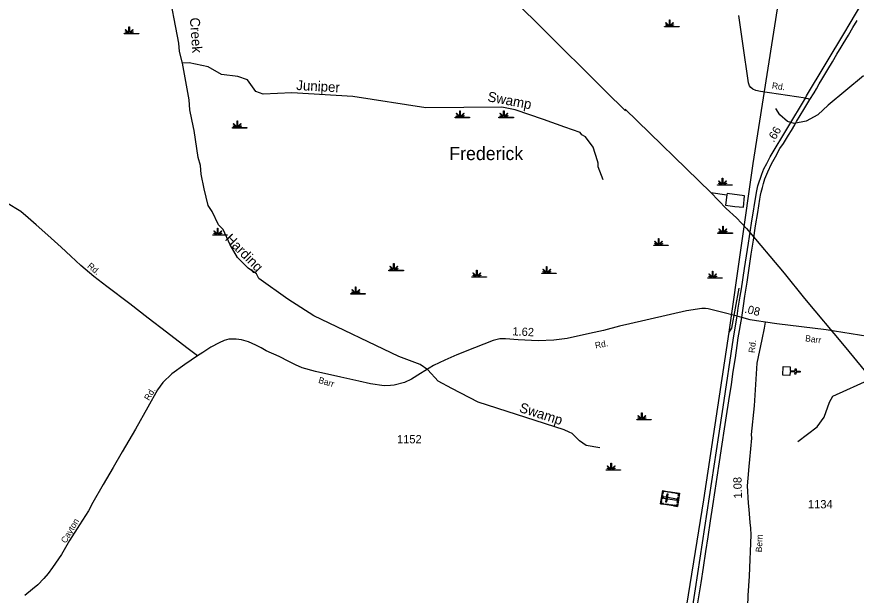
# Model space of a CAD drawing. Extents: x 2532689 to 2764727, y 536648 to 732970.
# Drawn here: x 2549089 to 2561755, y 627049 to 635778 of the extents above; entities that cross this region are included whole.
import ezdxf

# ---------------------------------------------------------------- set-up
doc = ezdxf.new("R2010")
doc.units = 0
for name, color, linetype in [('Exist Civil Demographics Community Label', 7, 'Continuous'), ('Exist Cultural Cemetery CELL', 7, 'Continuous'), ('Exist Cultural Church CELL', 7, 'Continuous'), ('Exist Hydrographic Creek Single Shore', 7, 'Continuous'), ('Exist Hydrographic Creek Single Shore Label', 7, 'Continuous'), ('Exist Hydrographic Swamp CELL', 7, 'Continuous'), ('Exist Hydrographic Swamp Label', 7, 'Continuous'), ('Exist Railroad Mainline', 7, 'Continuous'), ('Exist Railroad Siding', 7, 'Continuous'), ('Exist Road Primary US Divided Attributed', 7, 'Continuous'), ('Exist Road Primary US Mileage Hundredths English Label', 7, 'Continuous'), ('Exist Road Secondary Mileage Hundredths English Label', 7, 'Continuous'), ('Exist Road Secondary Type 51 Attributed', 7, 'Continuous'), ('Exist Road Secondary Type 51 Label', 7, 'Continuous'), ('Exist Road Secondary Type 51 Number Label', 7, 'Continuous'), ('Exist Utilities Electrical Transmission Line', 7, 'Continuous')]:
    doc.layers.add(name, color=color, linetype=linetype)

msp = doc.modelspace()

# ---------------------------------------------------------------- linework, layer by layer
at = {"layer": 'Exist Cultural Cemetery CELL'}
for points in [[(2558804, 628430), (2558835, 628626), (2559087, 628587), (2559056, 628390)], [(2558878, 628620), (2558876, 628609), (2558844, 628614), (2558838, 628574), (2558827, 628575), (2558835, 628627)], [(2558948, 628597), (2558906, 628604), (2558907, 628615), (2558950, 628608)], [(2559014, 628587), (2558971, 628594), (2558973, 628605), (2559015, 628598)], [(2558847, 628423), (2558849, 628434), (2558817, 628439), (2558823, 628479), (2558812, 628481), (2558804, 628430)], [(2558816, 628503), (2558824, 628554), (2558835, 628552), (2558827, 628501)], [(2558850, 628533), (2558847, 628514), (2559047, 628483), (2559050, 628501)], [(2558878, 628460), (2558896, 628457), (2558915, 628573), (2558896, 628576)], [(2559082, 628554), (2559070, 628556), (2559074, 628578), (2559034, 628584), (2559035, 628595), (2559087, 628587)], [(2559053, 628449), (2559067, 628532), (2559078, 628531), (2559065, 628447)], [(2558920, 628411), (2558877, 628418), (2558879, 628429), (2558922, 628423)], [(2558987, 628401), (2558944, 628408), (2558946, 628419), (2558988, 628412)], [(2559061, 628423), (2559049, 628425), (2559046, 628403), (2559006, 628409), (2559004, 628398), (2559056, 628390)]]:
    msp.add_lwpolyline(points, close=True, dxfattribs=at)
at = {"layer": 'Exist Cultural Church CELL'}
msp.add_lwpolyline([(2560760, 630495), (2560757, 630438), (2560833, 630433), (2560835, 630465), (2560851, 630464), (2560849, 630432), (2560909, 630429), (2560908, 630413), (2560848, 630416), (2560846, 630384), (2560830, 630385), (2560832, 630417), (2560756, 630422), (2560752, 630365), (2560646, 630371), (2560654, 630501)], close=True, dxfattribs=at)
at = {"layer": 'Exist Hydrographic Creek Single Shore'}
for points in [[(2551589, 635080), (2551544, 635256), (2551534, 635380), (2551368, 636250), (2551357, 636400), (2551313, 636510), (2551284, 636726), (2551247, 636931), (2551228, 637065), (2551173, 637306), (2551118, 637632), (2551108, 637713), (2550964, 637845), (2550619, 638005), (2550401, 638075), (2548712, 638838)], [(2557357, 634112), (2557038, 634230), (2556610, 634374), (2556410, 634412), (2555260, 634405), (2554157, 634577), (2553239, 634628), (2552806, 634611), (2552697, 634652), (2552569, 634824), (2552426, 634878), (2552176, 634907), (2551974, 635020), (2551689, 635081), (2551589, 635080)], [(2551757, 634109), (2551702, 634376), (2551691, 634523), (2551589, 635080)], [(2561864, 634888), (2561331, 634443), (2561175, 634299), (2561002, 634204), (2560819, 634167), (2560719, 634199), (2560600, 634299), (2560540, 634395)], [(2557425, 629512), (2557349, 629545), (2556050, 629962), (2555655, 630171), (2555448, 630278), (2555292, 630451), (2555173, 630530), (2554854, 630649), (2553573, 631266), (2553180, 631517), (2552740, 631827), (2552706, 631901), (2552579, 631982), (2552418, 632146), (2552306, 632335), (2552202, 632567), (2552134, 632640), (2552039, 632840), (2551979, 632929), (2551916, 633179), (2551870, 633401), (2551859, 633535), (2551824, 633652), (2551766, 634060), (2551757, 634109)], [(2557617, 633998), (2557592, 634033), (2557357, 634112)], [(2557938, 633315), (2557859, 633512), (2557859, 633571), (2557850, 633603), (2557787, 633811), (2557668, 633967), (2557617, 633998)], [(2560872, 629369), (2561167, 629591), (2561273, 629736), (2561352, 629963), (2561400, 630053), (2561978, 630316)], [(2557887, 629271), (2557678, 629309), (2557577, 629380), (2557467, 629487), (2557425, 629512)]]:
    msp.add_lwpolyline(points, dxfattribs=at)
at = {"layer": 'Exist Hydrographic Swamp CELL'}
for points in [[(2558864, 635631), (2558917, 635631), (2558919, 635635), (2558881, 635649), (2558884, 635655), (2558921, 635639), (2558923, 635642), (2558879, 635686), (2558884, 635691), (2558929, 635646), (2558935, 635648), (2558935, 635731), (2558943, 635731), (2558943, 635648), (2558949, 635646), (2558994, 635691), (2558999, 635686), (2558955, 635642), (2558957, 635638), (2558998, 635657), (2559000, 635652), (2558959, 635634), (2558961, 635631), (2559082, 635631), (2559082, 635624), (2558864, 635624)], [(2550710, 635527), (2550763, 635527), (2550765, 635531), (2550726, 635546), (2550729, 635551), (2550767, 635535), (2550769, 635538), (2550724, 635583), (2550729, 635588), (2550775, 635542), (2550781, 635545), (2550781, 635628), (2550788, 635628), (2550788, 635545), (2550795, 635542), (2550840, 635588), (2550845, 635583), (2550801, 635538), (2550803, 635535), (2550843, 635553), (2550846, 635548), (2550805, 635530), (2550807, 635527), (2550928, 635527), (2550928, 635520), (2550710, 635520)], [(2555703, 634261), (2555756, 634261), (2555758, 634264), (2555719, 634279), (2555722, 634284), (2555760, 634269), (2555762, 634272), (2555717, 634316), (2555722, 634321), (2555768, 634276), (2555774, 634278), (2555774, 634361), (2555781, 634361), (2555781, 634278), (2555788, 634276), (2555833, 634321), (2555838, 634316), (2555794, 634272), (2555796, 634268), (2555836, 634287), (2555839, 634282), (2555798, 634264), (2555799, 634261), (2555921, 634261), (2555921, 634254), (2555703, 634254)], [(2556364, 634261), (2556417, 634261), (2556419, 634264), (2556380, 634279), (2556383, 634284), (2556421, 634269), (2556423, 634272), (2556378, 634316), (2556383, 634321), (2556429, 634276), (2556435, 634278), (2556435, 634361), (2556442, 634361), (2556442, 634278), (2556449, 634276), (2556494, 634321), (2556499, 634316), (2556455, 634272), (2556457, 634268), (2556497, 634287), (2556500, 634282), (2556459, 634264), (2556461, 634261), (2556582, 634261), (2556582, 634254), (2556364, 634254)], [(2552342, 634106), (2552394, 634106), (2552396, 634110), (2552358, 634124), (2552361, 634130), (2552399, 634114), (2552400, 634117), (2552356, 634161), (2552361, 634166), (2552406, 634121), (2552412, 634123), (2552412, 634206), (2552420, 634206), (2552420, 634123), (2552426, 634121), (2552471, 634166), (2552476, 634161), (2552432, 634117), (2552434, 634113), (2552475, 634132), (2552477, 634127), (2552436, 634109), (2552438, 634106), (2552559, 634106), (2552559, 634099), (2552342, 634099)], [(2559663, 633242), (2559716, 633243), (2559718, 633246), (2559680, 633261), (2559683, 633266), (2559720, 633250), (2559722, 633253), (2559677, 633298), (2559683, 633303), (2559728, 633257), (2559734, 633260), (2559734, 633343), (2559741, 633343), (2559741, 633260), (2559748, 633257), (2559793, 633303), (2559798, 633298), (2559754, 633253), (2559756, 633250), (2559797, 633268), (2559799, 633263), (2559758, 633245), (2559760, 633243), (2559881, 633242), (2559881, 633235), (2559663, 633235)], [(2552046, 632487), (2552099, 632488), (2552101, 632491), (2552063, 632506), (2552065, 632511), (2552103, 632495), (2552105, 632498), (2552060, 632543), (2552066, 632548), (2552111, 632502), (2552117, 632505), (2552117, 632588), (2552124, 632588), (2552124, 632505), (2552131, 632502), (2552176, 632548), (2552181, 632543), (2552137, 632498), (2552139, 632495), (2552180, 632513), (2552182, 632508), (2552141, 632490), (2552143, 632488), (2552264, 632487), (2552264, 632480), (2552046, 632480)], [(2559669, 632516), (2559722, 632516), (2559724, 632519), (2559686, 632534), (2559689, 632539), (2559726, 632524), (2559728, 632526), (2559683, 632571), (2559689, 632576), (2559734, 632531), (2559740, 632533), (2559740, 632616), (2559747, 632616), (2559747, 632533), (2559754, 632531), (2559799, 632576), (2559804, 632571), (2559760, 632526), (2559762, 632523), (2559803, 632541), (2559805, 632536), (2559764, 632519), (2559766, 632516), (2559887, 632516), (2559887, 632509), (2559669, 632509)], [(2558699, 632333), (2558751, 632333), (2558753, 632336), (2558715, 632351), (2558718, 632356), (2558756, 632341), (2558757, 632343), (2558713, 632388), (2558718, 632393), (2558763, 632348), (2558770, 632350), (2558770, 632433), (2558777, 632433), (2558777, 632350), (2558783, 632348), (2558829, 632393), (2558834, 632388), (2558789, 632343), (2558791, 632340), (2558832, 632359), (2558835, 632353), (2558794, 632336), (2558795, 632333), (2558916, 632333), (2558916, 632326), (2558699, 632326)], [(2554704, 631953), (2554757, 631953), (2554759, 631956), (2554721, 631971), (2554724, 631976), (2554761, 631961), (2554763, 631964), (2554719, 632008), (2554724, 632013), (2554769, 631968), (2554775, 631970), (2554775, 632053), (2554783, 632053), (2554783, 631970), (2554789, 631968), (2554834, 632013), (2554839, 632008), (2554795, 631964), (2554797, 631960), (2554838, 631979), (2554840, 631973), (2554799, 631956), (2554801, 631953), (2554922, 631953), (2554922, 631946), (2554704, 631946)], [(2555956, 631854), (2556009, 631854), (2556011, 631858), (2555973, 631873), (2555975, 631878), (2556013, 631862), (2556015, 631865), (2555970, 631910), (2555975, 631915), (2556021, 631869), (2556027, 631872), (2556027, 631955), (2556034, 631955), (2556034, 631872), (2556041, 631869), (2556086, 631915), (2556091, 631910), (2556047, 631865), (2556049, 631861), (2556090, 631880), (2556092, 631875), (2556051, 631857), (2556053, 631854), (2556174, 631854), (2556174, 631847), (2555956, 631847)], [(2557011, 631910), (2557064, 631911), (2557066, 631914), (2557027, 631929), (2557030, 631934), (2557068, 631918), (2557070, 631921), (2557025, 631966), (2557030, 631971), (2557076, 631925), (2557082, 631928), (2557082, 632011), (2557089, 632011), (2557089, 631928), (2557096, 631925), (2557141, 631971), (2557146, 631966), (2557102, 631921), (2557104, 631918), (2557144, 631936), (2557147, 631931), (2557106, 631913), (2557108, 631911), (2557229, 631910), (2557229, 631903), (2557011, 631903)], [(2559515, 631840), (2559567, 631840), (2559569, 631844), (2559531, 631859), (2559534, 631864), (2559572, 631848), (2559573, 631851), (2559529, 631895), (2559534, 631901), (2559579, 631855), (2559585, 631858), (2559585, 631941), (2559593, 631941), (2559593, 631858), (2559599, 631855), (2559644, 631901), (2559649, 631895), (2559605, 631851), (2559607, 631847), (2559648, 631866), (2559650, 631861), (2559609, 631843), (2559611, 631840), (2559732, 631840), (2559732, 631833), (2559515, 631833)], [(2554128, 631601), (2554180, 631601), (2554182, 631605), (2554144, 631619), (2554147, 631625), (2554185, 631609), (2554186, 631612), (2554142, 631656), (2554147, 631661), (2554192, 631616), (2554199, 631618), (2554199, 631701), (2554206, 631701), (2554206, 631618), (2554212, 631616), (2554258, 631661), (2554263, 631656), (2554218, 631612), (2554220, 631608), (2554261, 631627), (2554264, 631622), (2554223, 631604), (2554224, 631601), (2554345, 631601), (2554345, 631594), (2554128, 631594)], [(2558446, 629701), (2558498, 629701), (2558500, 629705), (2558462, 629719), (2558465, 629725), (2558503, 629709), (2558504, 629712), (2558460, 629756), (2558465, 629761), (2558510, 629716), (2558517, 629718), (2558517, 629801), (2558524, 629801), (2558524, 629718), (2558530, 629716), (2558575, 629761), (2558581, 629756), (2558536, 629712), (2558538, 629708), (2558579, 629727), (2558581, 629722), (2558540, 629704), (2558542, 629701), (2558663, 629701), (2558663, 629694), (2558446, 629694)], [(2557982, 628941), (2558034, 628941), (2558036, 628945), (2557998, 628959), (2558001, 628965), (2558039, 628949), (2558040, 628952), (2557996, 628996), (2558001, 629001), (2558046, 628956), (2558052, 628958), (2558052, 629041), (2558060, 629041), (2558060, 628958), (2558066, 628956), (2558111, 629001), (2558116, 628996), (2558072, 628952), (2558074, 628948), (2558115, 628967), (2558117, 628962), (2558076, 628944), (2558078, 628941), (2558199, 628941), (2558199, 628934), (2557982, 628934)]]:
    msp.add_lwpolyline(points, close=True, dxfattribs=at)
at = {"layer": 'Exist Railroad Mainline'}
for points in [[(2559836, 631017), (2560198, 633565), (2560580, 635992), (2561345, 640971), (2561535, 642299), (2561640, 643031)], [(2559124, 626429), (2559455, 628488), (2559836, 631017)]]:
    msp.add_lwpolyline(points, dxfattribs=at)
at = {"layer": 'Exist Railroad Siding'}
msp.add_lwpolyline([(2559836, 631017), (2559878, 631080), (2559987, 631682)], dxfattribs=at)
at = {"layer": 'Exist Road Primary US Divided Attributed'}
for points in [[(2560987, 634551), (2561007, 634587), (2561581, 635545), (2561649, 635658), (2561760, 635844), (2561864, 636016), (2561980, 636211), (2562085, 636388), (2562163, 636518), (2562307, 636758), (2562445, 636986), (2562519, 637112), (2562643, 637320), (2562996, 637912), (2563069, 638047), (2563124, 638171), (2563159, 638272), (2563197, 638390)], [(2561055, 634529), (2561118, 634632), (2561154, 634693), (2561197, 634767), (2561236, 634833), (2561328, 634984), (2561396, 635098), (2561464, 635212), (2561527, 635318), (2561557, 635368), (2561637, 635501), (2561705, 635614), (2561770, 635722)], [(2559956, 631259), (2559975, 631379), (2560004, 631562), (2560023, 631675), (2560068, 631978), (2560128, 632364), (2560174, 632663), (2560249, 633127), (2560271, 633227), (2560330, 633404), (2560363, 633481), (2560404, 633566), (2560458, 633665), (2560987, 634551)], [(2560027, 631239), (2560053, 631415), (2560074, 631560), (2560107, 631774), (2560140, 631985), (2560172, 632198), (2560204, 632408), (2560237, 632624), (2560269, 632826), (2560301, 633025), (2560311, 633085), (2560321, 633132), (2560339, 633204), (2560355, 633261), (2560378, 633330), (2560420, 633436), (2560478, 633557), (2560535, 633666), (2560604, 633791), (2560657, 633864), (2560733, 633990), (2560776, 634061), (2560828, 634148), (2560856, 634196), (2560964, 634379), (2561055, 634529)], [(2559093, 625618), (2559329, 627145), (2559682, 629461), (2559748, 629889), (2559902, 630931), (2559956, 631259)], [(2559367, 626935), (2559413, 627238), (2559451, 627467), (2559485, 627709), (2559520, 627930), (2559556, 628170), (2559591, 628396), (2559627, 628631), (2559656, 628830), (2559693, 629062), (2559732, 629331), (2559767, 629562), (2559798, 629758), (2559834, 629983), (2559871, 630230), (2559900, 630426), (2559931, 630629), (2559956, 630816), (2559971, 630933), (2560027, 631239)]]:
    msp.add_lwpolyline(points, dxfattribs=at)
at = {"layer": 'Exist Road Secondary Type 51 Attributed'}
for points in [[(2560987, 634551), (2560312, 634651), (2560240, 634665), (2560195, 634684), (2560164, 634710), (2560143, 634736), (2560130, 634780), (2560043, 635375), (2559983, 635798)], [(2560987, 634551), (2561025, 634546), (2561055, 634529)], [(2551817, 630663), (2551657, 630783), (2551348, 631017), (2551072, 631229), (2550794, 631447), (2550450, 631706), (2550252, 631861), (2550057, 632024), (2549905, 632166), (2549760, 632299), (2549555, 632482), (2549382, 632640), (2549261, 632746), (2549150, 632838), (2548933, 632972)], [(2559956, 631259), (2559724, 631322), (2559521, 631370), (2559481, 631375), (2559423, 631377), (2559196, 631339), (2558341, 631142), (2558184, 631108), (2557943, 631044), (2557729, 630998), (2557395, 630922), (2557192, 630898), (2556958, 630890), (2556656, 630904), (2556465, 630917), (2556375, 630917), (2556279, 630895), (2555997, 630781), (2555729, 630676), (2555550, 630595), (2555374, 630517), (2555178, 630395), (2555043, 630311), (2554938, 630257), (2554784, 630219), (2554726, 630213), (2554631, 630211), (2554424, 630241), (2554250, 630279), (2553976, 630341), (2553594, 630425), (2553397, 630482), (2553294, 630528), (2553193, 630576), (2553046, 630649), (2552854, 630739), (2552778, 630781), (2552695, 630823), (2552586, 630871), (2552480, 630903), (2552397, 630913), (2552288, 630912), (2552220, 630893), (2552142, 630858), (2552015, 630790), (2551895, 630711), (2551817, 630663)], [(2560387, 631172), (2560252, 631192), (2560153, 631207), (2560027, 631239), (2559956, 631259)], [(2560081, 625615), (2560094, 626043), (2560126, 627043), (2560145, 627337), (2560170, 627959), (2560167, 628059), (2560153, 628147), (2560137, 628342), (2560128, 628438), (2560113, 628699), (2560124, 628814), (2560140, 628994), (2560151, 629098), (2560181, 629417), (2560177, 629474), (2560222, 629909), (2560261, 630550), (2560337, 630908), (2560369, 631077), (2560387, 631172)], [(2564377, 629999), (2564279, 630011), (2563683, 630140), (2563358, 630218), (2563289, 630242), (2563196, 630283), (2563069, 630361), (2562917, 630498), (2562752, 630668), (2562712, 630702), (2562625, 630765), (2562573, 630796), (2562514, 630825), (2562444, 630852), (2562307, 630892), (2561299, 631054), (2560558, 631146), (2560387, 631172)], [(2551817, 630663), (2551622, 630530), (2551427, 630391), (2551292, 630259), (2551210, 630146), (2551065, 629887), (2550879, 629556), (2550680, 629213), (2550542, 628977), (2550393, 628722), (2550238, 628450), (2550172, 628324), (2550036, 628112), (2549886, 627876), (2549761, 627664), (2549628, 627467), (2549564, 627378), (2549498, 627302), (2549407, 627208), (2549325, 627140), (2549209, 627043)]]:
    msp.add_lwpolyline(points, dxfattribs=at)
at = {"layer": 'Exist Utilities Electrical Transmission Line'}
for q in [(2558268, 634385), (2559805, 633093)]:
    msp.add_line((2559560, 633128), q, dxfattribs=at)
for points in [[(2550485, 642091), (2550758, 641816), (2551078, 641496), (2551416, 641162), (2551807, 640779), (2552200, 640385), (2552773, 639823), (2553500, 639096), (2554388, 638212), (2555128, 637476), (2556001, 636610), (2556993, 635630), (2557971, 634656), (2558273, 634360)], [(2559560, 633128), (2559791, 632887), (2559946, 632743), (2560097, 632582), (2560670, 631908), (2560972, 631526), (2561574, 630813), (2562154, 630101), (2563558, 628440), (2564613, 627170), (2566845, 624552)], [(2559805, 633093), (2559784, 632936), (2559921, 632917), (2560053, 632904), (2560071, 633076), (2559809, 633109), (2559805, 633093)]]:
    msp.add_lwpolyline(points, dxfattribs=at)

# ---------------------------------------------------------------- texts
at = {"layer": 'Exist Civil Demographics Community Label'}
msp.add_text('Frederick', height=200, dxfattribs=at).set_placement((2555615, 633615))
at = {"layer": 'Exist Hydrographic Creek Single Shore Label'}
msp.add_text('Creek', height=150, rotation=274.1288, dxfattribs=at).set_placement((2551699, 635761))
at = {"layer": 'Exist Hydrographic Swamp Label'}
for s, rotation, p in [('Juniper', 356.7879, (2553303, 634674)), ('Swamp', 349.2846, (2556183, 634505)), ('Harding', 314.431, (2552222, 632416)), ('Swamp', 342.2057, (2556659, 629818))]:
    msp.add_text(s, height=150, rotation=rotation, dxfattribs=at).set_placement(p)
at = {"layer": 'Exist Road Primary US Mileage Hundredths English Label'}
msp.add_text('.66', height=125, rotation=59.1695, dxfattribs=at).set_placement((2560510, 633874))
at = {"layer": 'Exist Road Secondary Mileage Hundredths English Label'}
for s, rotation, p in [('.08', 346.7895, (2560062, 631314)), ('1.62', 357.3061, (2556565, 630971)), ('1.08', 91.5069, (2560032, 628510))]:
    msp.add_text(s, height=125, rotation=rotation, dxfattribs=at).set_placement(p)
at = {"layer": 'Exist Road Secondary Type 51 Label'}
for s, rotation, p in [('Rd.', 352.0379, (2560478, 634695)), ('Rd.', 320.8564, (2550145, 632002)), ('Rd.', 11.0873, (2557823, 630770)), ('Rd.', 85.1002, (2560225, 630702)), ('Barr', 352.1698, (2560981, 630882)), ('Barr', 343.6336, (2553632, 630255)), ('Rd.', 59.0565, (2551085, 629978)), ('Cayton', 59.2674, (2549829, 627825)), ('Bern', 87.6717, (2560333, 627696))]:
    msp.add_text(s, height=95, rotation=rotation, dxfattribs=at).set_placement(p)
at = {"layer": 'Exist Road Secondary Type 51 Number Label'}
for s, p in [('1152', (2554826, 629341)), ('1134', (2561027, 628360))]:
    msp.add_text(s, height=125, dxfattribs=at).set_placement(p)

doc.saveas('drawing.dxf')
